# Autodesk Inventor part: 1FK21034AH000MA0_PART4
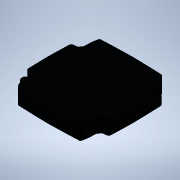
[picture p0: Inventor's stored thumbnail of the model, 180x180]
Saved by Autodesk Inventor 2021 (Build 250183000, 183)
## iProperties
Created: 2025-04
Part Number: 1FK21034AH000MA0_PART4
Material: Generic
Catalog Web Link: www.3dfindit.com
Description: -Servo synchronous motor
Document SubType Name: Modeling
Designer: psAdmin
Mass: 37.514 g
Surface Area: 101.697 cm^2
Volume: 37.514 cm^3
Density: 1 g/cm^3
Appearance: PSOLRGB-38-46-56
Category: PARTsolutions
Title: 1FK21034AH000MA0_PART4
Author: Cadenas PARTsolutions
Comments: Servo synchronous motor
Sending System: PARTsolutions
Preprocessor: ST-DEVELOPER v19.3
PSOL_IDENT_0: {$CADENAS_DATA/23d-libs/siemens_ag/_cat_/ec/b7/1fk21034ah000ma0.prj},213 {VTYP=3D},{NB=1FK21034AH000
PSOL_IDENT_1: MA0_PART4},{LINA=1FK21034AH000MA0_PART4},{NN=1FK21034AH000MA0_PART4},{NOPRJ=TRUE},{DATE=19.08.2025 1
PSOL_IDENT_2: 4:01:05},{GEOMDATE=30.07.2025 02:01:02},{VERSION=},{LINEID=10},{WBVAR=},{WBNUMERIC=}  {NB=1FK21034AH
PSOL_IDENT_3: 000MA0_PART4},{LINA=1FK21034AH000MA0_PART4},{KT=DUMMY},{PREVIEW=../../../_pool_/7c/50/p_d211_xx_0093
PSOL_IDENT_4: 2j.png},{DESCSHORT=SIMOTICS S-1FK2 HD, SINAMICS S210 3AC 400V-480V, 1.01 Nm, 4500 rpm},{DESCLONG=SIM
PSOL_IDENT_5: OTICS S-1FK2 HD servo motor M0=1.27 Nm; PN = 0.48 kW at nN=4500 rpm (380-480 V); PN = 0.3 kW at nN=2
PSOL_IDENT_6: 500 rpm (200-240 V); degree of protection IP64; cylindrical shaft D14 x 30 mm; absolute encoder 22-b
PSOL_IDENT_7: it + 12-bit multiturn (encoder AM22DQC); with OCC interface; plug size M17, rotatable; SIMOTICS S-1F
PSOL_IDENT_8: K2 servomotorfor a wide range of uses in industrial environments. SIMOTICS S‑1FK2 servomotors are co
PSOL_IDENT_9: mpact synchronous motors with a high dynamic performance that set themselves apart as a result of th
PSOL_IDENT_10: eir high power density, degree of protection and overload capability. The motors are available in tw
PSOL_IDENT_11: o variants: as High Dynamic variant (highest dynamic performance as a result of the low intrinsic mo
PSOL_IDENT_12: ment of inertia for applications demanding a high dynamic performance with low moved masses) - and a
PSOL_IDENT_13: s Compact variant (precise and stable closed-loop control for medium up to large moved masses as a r
PSOL_IDENT_14: esult of a medium intrinsic moment of inertia). SIMOTICSS‑1FK2 servomotors fully exploit their stren
PSOL_IDENT_15: gths in a system with the SINAMICSS210 frequency converter and simple connection using the one cable
PSOL_IDENT_16: connection (OCC). Advantages include the short control and positioning times, fast and precise corr
PSOL_IDENT_17: ection of disturbing quantities as well as stable control with a high dynamic performance. The servo
PSOL_IDENT_18: motors can be configured to address a wide range of requirements. For example with and without hold
PSOL_IDENT_19: ing brake, IP64 or IP65 degree of protection, singleturn or multiturn absolute encoders - to name ju
PSOL_IDENT_20: st a few. Further, the servomotors are available in different shaft heights extending from 20 to 100
PSOL_IDENT_21: . A shaft sealing ring is available to achieve an IP65 degree of protection and for subsequent mount
PSOL_IDENT_22: ing at the motor or as spare part. SIMOTICS - the optimum motor for each and every motion control ap
PSOL_IDENT_23: plication.},{INTNO=4034106444822},{SUPPLIERALTNO=1FK2103-4AH00-0MA0},{MANUID=1FK21034AH000MA0},{MANU
PSOL_IDENT_24: NAME=Siemens},{MANUTYPEDESC=SYNCHRONOUS MOTOR 1FK2 HD 1,27 NM},{AAU732=SIMOTICS},{AAO057=S-1FK2},{AA
PSOL_IDENT_25: U734=SIMOTICS S-1FK2 HD servo motor M0=1.27 Nm; PN = 0.48 kW at nN=4500 rpm (380-480 V); PN = 0.3 kW
PSOL_IDENT_26: at nN=2500 rpm (200-240 V); degree of protection IP64; cylindrical shaft D14 x 30 mm; absolute enco
PSOL_IDENT_27: der 22-bit + 12-bit multiturn (encoder AM22DQC); with OCC interface; plug size M17, rotatable;},{AAW
PSOL_IDENT_28: 338=SYNCHRONOUS MOTOR 1FK2 HD 1,27 NM},{AAO742=SIMOTICS},{AAO663=4034106444822},{NOCUPEROU=1},{PRICE
PSOL_IDENT_29: QUANTITY=1},{QUANTITYMIN=1},{QUANTITYINT=1},{CTN=85015100},{COO=RO},{AAO676=1FK2103-4AH00-0MA0},{AAO
PSOL_IDENT_30: 677=Siemens AG},{ORDERUNIT=C62},{CONTENTUNIT=C62}
NB: 1FK21034AH000MA0_PART4
NT: Servo synchronous motor
NBSYN: $MANUID._PART4
LINA: 1FK21034AH000MA0_PART4
CATALOG: SIEMENS
PREVIEW: ../../../_pool_/7c/50/p_d211_xx_00932j.png
DESCSHORT: SIMOTICS S-1FK2 HD, SINAMICS S210 3AC 400V-480V, 1.01 Nm, 4500 rpm
DESCLONG: SIMOTICS S-1FK2 HD servo motor M0=1.27 Nm; PN = 0.48 kW at nN=4500 rpm (380-480 V); PN = 0.3 kW at nN=2500 rpm (200-240 V); degree of protection IP64; cylindric
INTNO: 4034106444822
SUPPLIERALTNO: 1FK2103-4AH00-0MA0
MANUID: 1FK21034AH000MA0
MANUNAME: Siemens
MANUTYPEDESC: SYNCHRONOUS MOTOR 1FK2 HD 1,27 NM
AAU732: SIMOTICS
AAO057: S-1FK2
AAU734: SIMOTICS S-1FK2 HD servo motor M0=1.27 Nm; PN = 0.48 kW at nN=4500 rpm (380-480 V); PN = 0.3 kW at nN=2500 rpm (200-240 V); degree of protection IP64; cylindric
AAW338: SYNCHRONOUS MOTOR 1FK2 HD 1,27 NM
AAO742: SIMOTICS
AAO663: 4034106444822.0
NOCUPEROU: 1
PRICEQUANTITY: 1
QUANTITYMIN: 1
QUANTITYINT: 1
CTN: 85015100
COO: RO
ARTICLENO: 1FK21034AH000MA0_PART4
BOMINFO: 1FK21034AH000MA0_PART4
CREATOR: CADENAS GmbH
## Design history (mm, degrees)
feature "2025_04_17_15_01_37_0220"
body "Solid1"
